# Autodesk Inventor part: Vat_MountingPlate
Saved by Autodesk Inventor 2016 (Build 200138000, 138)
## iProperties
Created: 2015-11
Part Number: Vat_MountingPlate
Material: Generic
Document SubType Name: Modeling
Designer: John
Density: 1 g/cm^3
Appearance: Default
Author: John
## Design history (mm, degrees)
feature "Base1"
body "Solid1"
